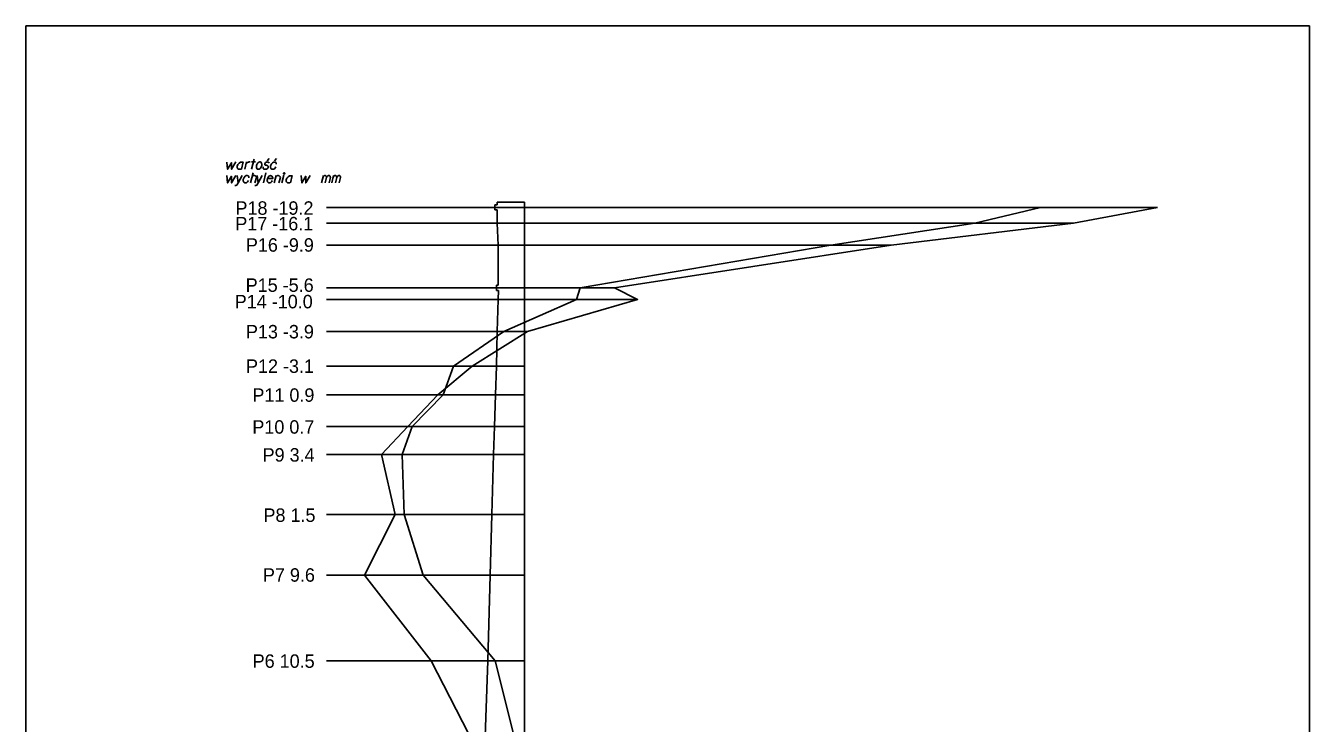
# Model space of a CAD drawing. Extents: x 138 to 264, y -75 to 121.
# Drawn here: x 227.52 to 248.52, y -45.34 to -33.92 of the extents above; entities that cross this region are included whole.
import ezdxf

# ---------------------------------------------------------------- set-up
doc = ezdxf.new("R2010")
doc.units = 0
for name, color, linetype in [('15 listopad 2008', 7, 'Continuous'), ('Ramka do drukowania', 7, 'Continuous'), ('Standart wykresów', 7, 'Continuous'), ('Wykresy 4 maj 2008', 7, 'Continuous')]:
    doc.layers.add(name, color=color, linetype=linetype)

msp = doc.modelspace()

# ---------------------------------------------------------------- linework, layer by layer
at = {"layer": '15 listopad 2008'}
msp.add_lwpolyline([(235.685, -52.61), (236.155, -51.164), (236.315, -49.788), (236.145, -48.421), (235.985, -47.063), (235.555, -45.704), (235.205, -44.313), (234.025, -42.911), (233.715, -41.918), (233.685, -40.937), (233.845, -40.478), (234.355, -39.961), (234.525, -39.493), (235.345, -38.925), (236.535, -38.4), (236.595, -38.212), (240.695, -37.514), (243.055, -37.151), (244.125, -36.895)], dxfattribs=at)
at = {"layer": 'Ramka do drukowania'}
for p, q in [((227.525, -33.921), (248.525, -33.921)), ((227.525, -63.621), (227.525, -33.921)), ((248.525, -63.621), (248.525, -33.921))]:
    msp.add_line(p, q, dxfattribs=at)
at = {"layer": 'Standart wykresów'}
for p, q in [((235.685, -36.895), (232.448, -36.895)), ((235.202, -36.853), (235.202, -36.895)), ((235.24, -36.853), (235.202, -36.853)), ((235.202, -36.895), (235.202, -36.937)), ((235.24, -36.937), (235.202, -36.937)), ((235.24, -36.811), (235.24, -36.853)), ((235.24, -36.811), (235.685, -36.811)), ((235.24, -37.151), (235.24, -36.937)), ((235.685, -56.895), (235.685, -36.811)), ((235.685, -37.151), (232.448, -37.151)), ((235.255, -37.514), (235.24, -37.151)), ((235.685, -37.514), (232.448, -37.514)), ((235.255, -37.514), (235.255, -38.168)), ((235.685, -38.212), (232.448, -38.212)), ((235.225, -38.168), (235.225, -38.212)), ((235.225, -38.168), (235.255, -38.168)), ((235.225, -38.212), (235.225, -38.256)), ((235.685, -38.4), (232.448, -38.4)), ((235.259, -38.256), (235.225, -38.256)), ((235.24, -38.925), (235.255, -38.4)), ((235.255, -38.4), (235.259, -38.256)), ((235.345, -38.925), (232.448, -38.925)), ((235.225, -39.493), (235.24, -38.925)), ((235.345, -38.925), (235.733, -38.925)), ((234.525, -39.493), (232.448, -39.493)), ((235.21, -39.961), (235.225, -39.493)), ((234.265, -39.961), (232.448, -39.961)), ((235.197, -40.478), (235.21, -39.961)), ((233.777, -40.478), (232.448, -40.478)), ((235.18, -40.937), (235.197, -40.478)), ((233.344, -40.937), (232.448, -40.937)), ((235.153, -41.918), (235.18, -40.937)), ((233.567, -41.918), (232.448, -41.918)), ((235.123, -42.911), (235.153, -41.918)), ((233.07, -42.911), (232.448, -42.911)), ((235.083, -44.313), (235.123, -42.911)), ((234.156, -44.313), (232.448, -44.313)), ((235.038, -45.704), (235.083, -44.313))]:
    msp.add_line(p, q, dxfattribs=at)
for points in [[(231.221, -36.271), (231.265, -36.105)], [(231.509, -36.093), (231.476, -36.13)], [(231.626, -36.095), (231.593, -36.131)], [(230.818, -36.152), (230.829, -36.271), (230.892, -36.163), (230.893, -36.271), (230.962, -36.15)], [(231.083, -36.161), (231.073, -36.155), (231.051, -36.155), (231.038, -36.157), (231.015, -36.171), (230.995, -36.194), (230.986, -36.219), (230.985, -36.232), (230.986, -36.242), (230.99, -36.252), (230.998, -36.262), (231.007, -36.269), (231.021, -36.271), (231.032, -36.27), (231.042, -36.269), (231.056, -36.261)], [(231.085, -36.151), (231.054, -36.271)], [(231.108, -36.271), (231.14, -36.147)], [(231.132, -36.177), (231.139, -36.172), (231.153, -36.161), (231.169, -36.155), (231.181, -36.151), (231.199, -36.147)], [(231.201, -36.494), (231.244, -36.328)], [(231.221, -36.151), (231.284, -36.151)], [(231.353, -36.151), (231.363, -36.151), (231.373, -36.156), (231.384, -36.171), (231.385, -36.177), (231.386, -36.184), (231.386, -36.189), (231.386, -36.208), (231.382, -36.222), (231.376, -36.237), (231.368, -36.25), (231.355, -36.262), (231.343, -36.271), (231.323, -36.271), (231.316, -36.269), (231.308, -36.262), (231.304, -36.256), (231.299, -36.24), (231.299, -36.216), (231.301, -36.208), (231.306, -36.191), (231.312, -36.182), (231.314, -36.177), (231.327, -36.163), (231.34, -36.155), (231.353, -36.151)], [(231.509, -36.171), (231.505, -36.161), (231.496, -36.155), (231.488, -36.152), (231.476, -36.151), (231.466, -36.152), (231.45, -36.16), (231.44, -36.171), (231.436, -36.18), (231.435, -36.19), (231.437, -36.197), (231.442, -36.201), (231.445, -36.202), (231.453, -36.205), (231.462, -36.206), (231.475, -36.208), (231.483, -36.211), (231.49, -36.219), (231.492, -36.228), (231.491, -36.24), (231.486, -36.25), (231.475, -36.262), (231.466, -36.267), (231.456, -36.27), (231.442, -36.271), (231.427, -36.27), (231.416, -36.265), (231.411, -36.258), (231.408, -36.249), (231.408, -36.24), (231.412, -36.232)], [(231.413, -36.494), (231.456, -36.328)], [(231.624, -36.186), (231.623, -36.171), (231.616, -36.16), (231.609, -36.155), (231.593, -36.152), (231.579, -36.152), (231.56, -36.164), (231.546, -36.184), (231.535, -36.203), (231.531, -36.218), (231.531, -36.24), (231.533, -36.248), (231.538, -36.258), (231.55, -36.269), (231.563, -36.271), (231.577, -36.27), (231.585, -36.267), (231.602, -36.256), (231.615, -36.233)], [(231.75, -36.328), (231.757, -36.328), (231.761, -36.33), (231.764, -36.335), (231.764, -36.342), (231.761, -36.347), (231.757, -36.35), (231.75, -36.35), (231.746, -36.347), (231.742, -36.342), (231.742, -36.335), (231.746, -36.33), (231.75, -36.328)], [(230.817, -36.375), (230.828, -36.494), (230.89, -36.385), (230.892, -36.494), (230.961, -36.372)], [(231.067, -36.372), (231, -36.494), (230.979, -36.529), (230.974, -36.532), (230.968, -36.534), (230.955, -36.537), (230.949, -36.537)], [(230.983, -36.373), (231, -36.494)], [(231.178, -36.409), (231.177, -36.393), (231.17, -36.383), (231.163, -36.377), (231.147, -36.375), (231.133, -36.375), (231.114, -36.386), (231.1, -36.406), (231.089, -36.426), (231.085, -36.44), (231.085, -36.462), (231.087, -36.47), (231.092, -36.481), (231.104, -36.491), (231.117, -36.494), (231.131, -36.492), (231.139, -36.49), (231.156, -36.478), (231.169, -36.456)], [(231.225, -36.398), (231.229, -36.393), (231.235, -36.385), (231.239, -36.381), (231.241, -36.379), (231.245, -36.376), (231.249, -36.375), (231.253, -36.373), (231.257, -36.372), (231.266, -36.372), (231.273, -36.373), (231.28, -36.376), (231.286, -36.379), (231.29, -36.383), (231.293, -36.388), (231.296, -36.392), (231.297, -36.394), (231.3, -36.4), (231.3, -36.403), (231.275, -36.494)], [(231.394, -36.372), (231.327, -36.494), (231.307, -36.529), (231.301, -36.532), (231.295, -36.534), (231.282, -36.537), (231.276, -36.537)], [(231.31, -36.373), (231.327, -36.494)], [(231.482, -36.424), (231.566, -36.424), (231.567, -36.411), (231.564, -36.4), (231.559, -36.388), (231.543, -36.376), (231.53, -36.375), (231.52, -36.377), (231.505, -36.385), (231.496, -36.394), (231.488, -36.409), (231.483, -36.419), (231.478, -36.441), (231.478, -36.456), (231.479, -36.468), (231.483, -36.478), (231.499, -36.492), (231.509, -36.494), (231.52, -36.492), (231.521, -36.492), (231.538, -36.485), (231.547, -36.475), (231.551, -36.469), (231.553, -36.468), (231.559, -36.456)], [(231.589, -36.494), (231.622, -36.373)], [(231.614, -36.402), (231.618, -36.396), (231.623, -36.388), (231.627, -36.384), (231.632, -36.379), (231.638, -36.376), (231.644, -36.373), (231.651, -36.372), (231.656, -36.372), (231.662, -36.373), (231.668, -36.376), (231.673, -36.379), (231.678, -36.383), (231.683, -36.388), (231.686, -36.392), (231.689, -36.397), (231.691, -36.403), (231.668, -36.494)], [(231.713, -36.494), (231.747, -36.367)], [(231.885, -36.384), (231.876, -36.377), (231.853, -36.377), (231.84, -36.38), (231.817, -36.393), (231.797, -36.417), (231.788, -36.441), (231.787, -36.455), (231.788, -36.465), (231.792, -36.474), (231.8, -36.485), (231.809, -36.491), (231.823, -36.494), (231.834, -36.492), (231.844, -36.491), (231.859, -36.483)], [(231.887, -36.373), (231.856, -36.494)], [(232.033, -36.375), (232.043, -36.494), (232.106, -36.385), (232.107, -36.494), (232.177, -36.372)], [(232.365, -36.494), (232.395, -36.375)], [(232.387, -36.406), (232.394, -36.392), (232.4, -36.384), (232.408, -36.379), (232.416, -36.375), (232.421, -36.372), (232.429, -36.372), (232.432, -36.373), (232.437, -36.379), (232.442, -36.385), (232.446, -36.397), (232.447, -36.403), (232.454, -36.392), (232.462, -36.384), (232.47, -36.379), (232.478, -36.375), (232.484, -36.372), (232.491, -36.372), (232.496, -36.373), (232.5, -36.379), (232.504, -36.385), (232.508, -36.397), (232.509, -36.403), (232.487, -36.494)], [(232.425, -36.494), (232.447, -36.403)], [(232.531, -36.494), (232.561, -36.375)], [(232.553, -36.406), (232.56, -36.392), (232.567, -36.384), (232.574, -36.379), (232.582, -36.375), (232.587, -36.372), (232.595, -36.372), (232.598, -36.373), (232.603, -36.379), (232.608, -36.385), (232.612, -36.397), (232.614, -36.403), (232.62, -36.392), (232.628, -36.384), (232.636, -36.379), (232.644, -36.375), (232.65, -36.372), (232.657, -36.372), (232.662, -36.373), (232.666, -36.379), (232.67, -36.385), (232.674, -36.397), (232.675, -36.403), (232.653, -36.494)], [(232.591, -36.494), (232.614, -36.403)]]:
    msp.add_lwpolyline(points, dxfattribs=at)
at = {"layer": 'Wykresy 4 maj 2008'}
for p, q in [((235.685, -36.895), (246.042, -36.895)), ((235.685, -37.151), (244.665, -37.151)), ((235.685, -37.514), (241.683, -37.514)), ((235.685, -38.212), (237.155, -38.212)), ((235.685, -38.4), (237.534, -38.4)), ((235.685, -39.493), (234.525, -39.493)), ((235.685, -39.961), (234.265, -39.961)), ((235.685, -40.478), (233.777, -40.478)), ((235.685, -40.937), (233.344, -40.937)), ((235.685, -41.918), (233.567, -41.918)), ((235.685, -42.911), (233.07, -42.911)), ((235.685, -44.313), (234.156, -44.313))]:
    msp.add_line(p, q, dxfattribs=at)
msp.add_lwpolyline([(235.685, -52.61), (235.666, -51.164), (235.639, -49.788), (235.677, -48.421), (235.319, -47.063), (234.872, -45.704), (234.156, -44.313), (233.07, -42.911), (233.567, -41.918), (233.344, -40.937), (233.777, -40.478), (234.265, -39.961), (234.83, -39.493), (235.733, -38.925), (237.534, -38.4), (237.155, -38.212), (241.683, -37.514), (244.665, -37.151), (246.042, -36.895)], dxfattribs=at)

# ---------------------------------------------------------------- texts
for s, p in [('P18 -19.2', (230.957, -37.015)), ('P17 -16.1', (230.954, -37.27)), ('P16 -9.9', (231.127, -37.619)), ('P15 -5.6', (231.124, -38.276)), ('P14 -10.0', (230.945, -38.546)), ('P13 -3.9', (231.128, -39.038)), ('P12 -3.1', (231.129, -39.602)), ('P11 0.9', (231.234, -40.075)), ('P10 0.7', (231.233, -40.597)), ('P9 3.4', (231.401, -41.054)), ('P8 1.5', (231.415, -42.04)), ('P7 9.6', (231.406, -43.019)), ('P6 10.5', (231.238, -44.428))]:
    msp.add_text(s, height=0.22, dxfattribs=at).set_placement(p)

doc.saveas('drawing.dxf')
